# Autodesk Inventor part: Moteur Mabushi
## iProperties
Author: Flavien MARTY
Shininess: 86.0
PropertySet Name: _Private Model Information
Created: 2001-10
Part Number: Moteur Mabushi
Material: Par défaut
Document SubType Name: Modélisation
Designer: Flavien MARTY
Control State: 0
Master: False
Checked Out: False
PropertySet Name: Design Tracking Control
Density: 0.0
Volumn: 0.0
Area: 0.0
PropertySet Name: Model Information
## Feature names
1. Base1
